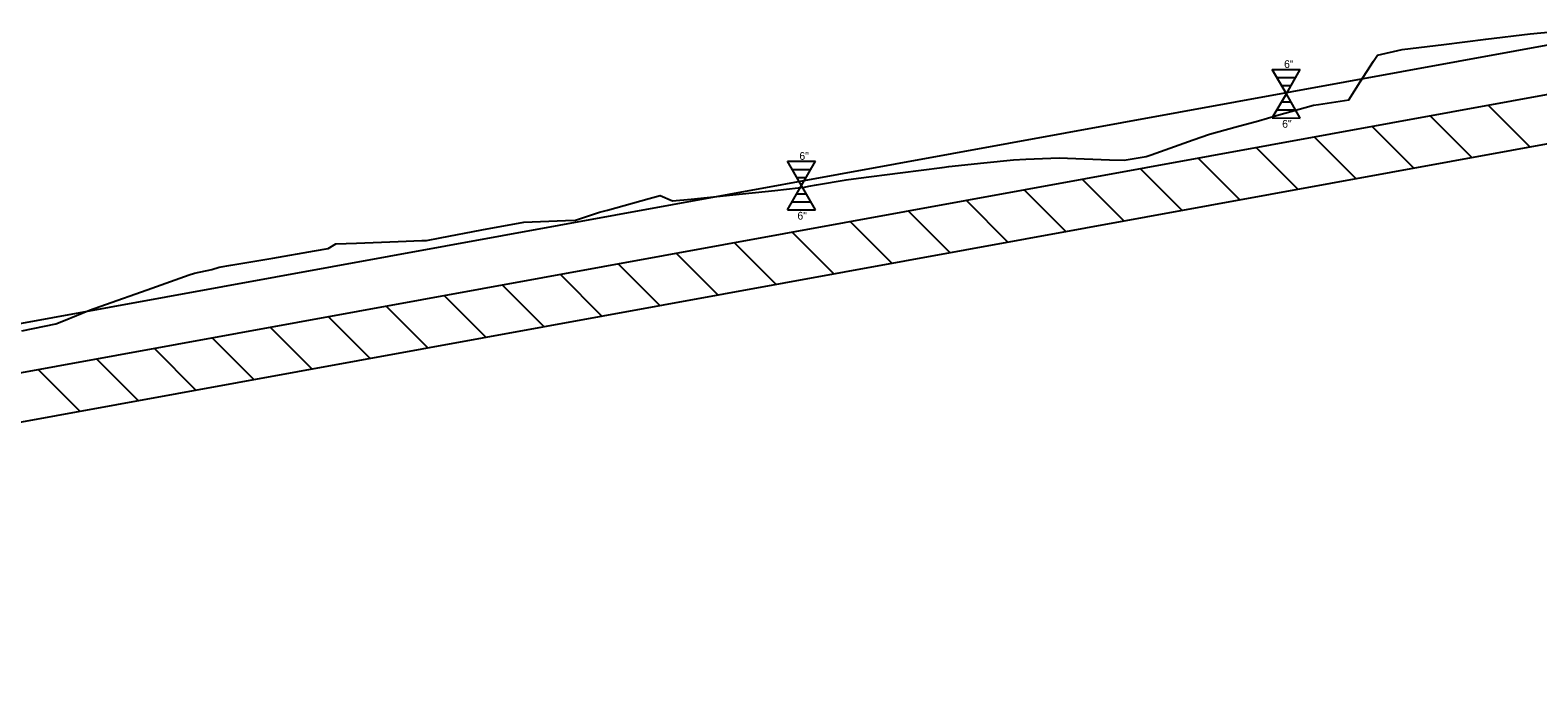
# Model space of a CAD drawing. Extents: x 579185 to 595036, y -53221 to -44640.
# Drawn here: x 584196.7 to 584352.2, y -46885.4 to -46818.8 of the extents above; entities that cross this region are included whole.
import ezdxf

# ---------------------------------------------------------------- set-up
doc = ezdxf.new("R2010")
doc.units = 0
for name, color, linetype in [('Exist Vertical Profile Ground Line', 7, 'Continuous'), ('Old_Level_2', 7, 'Continuous'), ('Prop Vertical Profile Grade', 7, 'Continuous'), ('Scratch_Level_1', 7, 'Continuous')]:
    doc.layers.add(name, color=color, linetype=linetype)

msp = doc.modelspace()

# ---------------------------------------------------------------- linework, layer by layer
at = {"layer": 'Exist Vertical Profile Ground Line'}
for points in [[(584262.91, -46836.41), (584264.83, -46836.21), (584269.15, -46835.77), (584273.46, -46835.32), (584275.9, -46835.06), (584276.53, -46834.97), (584276.97, -46834.89), (584277.78, -46834.75), (584280.82, -46834.22), (584282.09, -46834.06), (584286.41, -46833.51), (584290.72, -46832.95), (584291.44, -46832.86), (584295.03, -46832.49), (584298.08, -46832.16), (584299.35, -46832.11), (584302.81, -46831.97), (584303.66, -46832), (584307.98, -46832.16), (584309.52, -46832.21), (584311.77, -46831.82), (584312.29, -46831.64), (584316.61, -46830.12), (584318.3, -46829.53), (584320.92, -46828.81), (584323.35, -46828.15), (584325.23, -46827.6), (584329.03, -46826.52), (584329.55, -46826.45), (584332.67, -46825.97), (584333.86, -46824.13), (584335.23, -46822.01), (584335.65, -46821.39), (584338.18, -46820.81), (584342.49, -46820.28), (584346.81, -46819.74), (584351.4, -46819.17), (584355.43, -46818.8)], [(584195.81, -46849.81), (584199.31, -46849.08), (584200.12, -46848.75), (584202.78, -46847.67), (584204.43, -46847.08), (584208.75, -46845.56), (584213.06, -46844.03), (584213.62, -46843.84), (584215.42, -46843.49), (584216.15, -46843.24), (584217.38, -46843.03), (584221.69, -46842.29), (584226.01, -46841.55), (584227.39, -46841.31), (584228.21, -46840.84), (584230.32, -46840.76), (584234.63, -46840.6), (584237.07, -46840.5), (584237.54, -46840.48), (584238.95, -46840.21), (584243.26, -46839.39), (584247.58, -46838.58), (584251.89, -46838.43), (584252.91, -46838.4), (584255.38, -46837.58), (584256.21, -46837.35), (584260.52, -46836.15), (584261.66, -46835.83), (584262.91, -46836.41)]]:
    msp.add_lwpolyline(points, dxfattribs=at)
at = {"layer": 'Old_Level_2'}
for p, q in [((584326.24, -46825.35), (584324.79, -46822.85)), ((584324.79, -46822.85), (584327.68, -46822.85)), ((584326.24, -46825.35), (584327.68, -46822.85)), ((584325.27, -46823.69), (584327.2, -46823.69)), ((584324.79, -46827.85), (584326.24, -46825.35)), ((584325.76, -46824.52), (584326.72, -46824.52)), ((584327.68, -46827.86), (584326.24, -46825.35)), ((584325.27, -46827.02), (584327.2, -46827.02)), ((584325.75, -46826.19), (584326.72, -46826.19)), ((584324.79, -46827.85), (584327.68, -46827.86)), ((584276.24, -46834.82), (584274.79, -46832.32)), ((584274.79, -46832.32), (584277.68, -46832.32)), ((584275.27, -46833.16), (584277.2, -46833.16)), ((584276.24, -46834.82), (584277.68, -46832.32)), ((584274.79, -46837.32), (584276.24, -46834.82)), ((584275.76, -46833.99), (584276.72, -46833.99)), ((584277.68, -46837.33), (584276.24, -46834.82)), ((584275.27, -46836.49), (584277.2, -46836.49)), ((584275.75, -46835.66), (584276.72, -46835.66)), ((584274.79, -46837.32), (584277.68, -46837.33))]:
    msp.add_line(p, q, dxfattribs=at)
at = {"layer": 'Prop Vertical Profile Grade'}
msp.add_line((583996.24, -46885.36), (584356.24, -46819.78), dxfattribs=at)
at = {"layer": 'Scratch_Level_1'}
for p, q in [((584176.24, -46857.65), (584357.13, -46824.7)), ((584347.04, -46826.54), (584351.34, -46830.84)), ((584335.08, -46828.72), (584339.38, -46833.02)), ((584341.06, -46827.63), (584345.36, -46831.93)), ((584176.24, -46862.74), (584358.03, -46829.62)), ((584329.1, -46829.81), (584333.39, -46834.1)), ((584317.13, -46831.98), (584321.43, -46836.28)), ((584323.11, -46830.9), (584327.41, -46835.19)), ((584311.15, -46833.07), (584315.45, -46837.37)), ((584299.19, -46835.25), (584303.49, -46839.55)), ((584305.17, -46834.16), (584309.47, -46838.46)), ((584293.21, -46836.34), (584297.51, -46840.64)), ((584287.23, -46837.43), (584291.52, -46841.73)), ((584275.26, -46839.61), (584279.56, -46843.91)), ((584281.24, -46838.52), (584285.54, -46842.82)), ((584269.28, -46840.7), (584273.58, -46845)), ((584257.32, -46842.88), (584261.62, -46847.18)), ((584263.3, -46841.79), (584267.6, -46846.09)), ((584251.34, -46843.97), (584255.64, -46848.27)), ((584239.37, -46846.15), (584243.67, -46850.45)), ((584245.36, -46845.06), (584249.65, -46849.36)), ((584233.39, -46847.24), (584237.69, -46851.54)), ((584227.41, -46848.33), (584231.71, -46852.63)), ((584215.45, -46850.51), (584219.75, -46854.81)), ((584221.43, -46849.42), (584225.73, -46853.72)), ((584209.47, -46851.6), (584213.77, -46855.9)), ((584197.5, -46853.78), (584201.8, -46858.08)), ((584203.49, -46852.69), (584207.79, -46856.99))]:
    msp.add_line(p, q, dxfattribs=at)

# ---------------------------------------------------------------- texts
at = {"layer": 'Old_Level_2'}
for p in [(584326.01, -46822.7), (584325.81, -46828.86), (584276.01, -46832.17), (584275.81, -46838.33)]:
    msp.add_text('6"', height=0.8, dxfattribs=at).set_placement(p)

doc.saveas('drawing.dxf')
